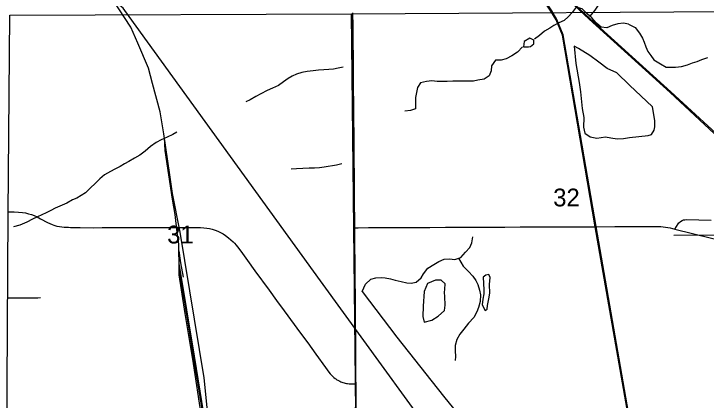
# Model space of a CAD drawing. Extents: x 0 to 40.2, y 0 to 22.
# Drawn here: x 2.971 to 4.597, y 16.354 to 17.261 of the extents above; entities that cross this region are included whole.
import ezdxf

# ---------------------------------------------------------------- set-up
doc = ezdxf.new("R2010")
doc.units = 0
for name, color, linetype in [('GM_X_City_Street', 7, 'Continuous'), ('GM_X_Corporation', 7, 'Continuous'), ('GM_X_Major_Lake_Text', 7, 'Continuous'), ('GM_X_Major_River', 7, 'Continuous'), ('GM_X_Minor_Lake', 7, 'Continuous'), ('GM_X_Minor_Lake_Text', 7, 'Continuous'), ('GM_X_Rail_Line', 7, 'Continuous'), ('GM_X_Unincorporated_Location', 7, 'Continuous')]:
    doc.layers.add(name, color=color, linetype=linetype)

msp = doc.modelspace()

# ---------------------------------------------------------------- linework, layer by layer
at = {"layer": 'GM_X_Corporation'}
for points in [[(2.9622, 17.2582), (3.7642, 17.2609), (3.7748, 16.2549), (3.7456, 16.2537), (2.955, 16.2539), (2.9579, 16.7917)], [(4.773, 17.2675), (4.7705, 16.2552), (4.7398, 16.2563), (3.7748, 16.2549), (3.7642, 17.2609)]]:
    msp.add_lwpolyline(points, close=True, dxfattribs=at)
at = {"layer": 'GM_X_Major_Lake_Text'}
for points in [[(3.768, 17.2235), (3.7677, 17.2315), (3.7674, 17.2634)], [(3.772, 16.7585), (3.7718, 16.779), (3.7713, 16.8131), (3.771, 16.8809), (3.7704, 16.9176), (3.7703, 16.9455), (3.7703, 16.9759), (3.7699, 17.0132), (3.7698, 17.0299), (3.7695, 17.0489), (3.7692, 17.0873), (3.7687, 17.1333), (3.7686, 17.1507), (3.7686, 17.1644), (3.7683, 17.188), (3.768, 17.2235)], [(3.7748, 16.3921), (3.7747, 16.4005), (3.7747, 16.4061), (3.7747, 16.4142), (3.7745, 16.4241), (3.7744, 16.431), (3.7743, 16.4378), (3.7742, 16.4453), (3.7741, 16.4558), (3.774, 16.462), (3.7741, 16.4689), (3.7741, 16.4881), (3.7741, 16.4943), (3.774, 16.5049), (3.7737, 16.5322), (3.7736, 16.5416), (3.7735, 16.5546), (3.7733, 16.5764), (3.7733, 16.6031), (3.7731, 16.6285), (3.7727, 16.6596), (3.7726, 16.6758), (3.7723, 16.718), (3.772, 16.7585)], [(3.767, 16.2555), (3.7693, 16.2747), (3.7715, 16.2932), (3.7729, 16.3087), (3.7739, 16.3273), (3.7746, 16.3484), (3.7748, 16.3688), (3.7748, 16.3921)]]:
    msp.add_lwpolyline(points, dxfattribs=at)
at = {"layer": 'GM_X_Major_River'}
for p, q in [((3.3597, 16.6749), (3.359, 16.7047)), ((3.3595, 16.6608), (3.3597, 16.6749))]:
    msp.add_line(p, q, dxfattribs=at)
for points in [[(3.4275, 16.3124), (3.4214, 16.3755), (3.4184, 16.4064), (3.362, 16.7482), (3.3443, 16.8388), (3.338, 16.8832), (3.3236, 16.9789), (3.3149, 17.0308), (3.2968, 17.0973), (3.2873, 17.1335), (3.2626, 17.1924), (3.2465, 17.2295), (3.2047, 17.2941), (3.141, 17.3854), (3.1259, 17.4137)], [(4.4984, 15.8177), (4.4509, 16.1036), (4.3365, 16.7608), (4.2596, 17.2111), (4.2446, 17.2471), (4.2325, 17.2675), (4.2194, 17.2862), (4.173, 17.3292), (4.0811, 17.4144)], [(4.5011, 15.819), (4.4528, 16.1039), (4.3383, 16.7612), (4.2614, 17.2116), (4.2462, 17.2479), (4.2341, 17.2685), (4.2208, 17.2874), (4.1742, 17.3305), (4.0824, 17.4158)], [(4.1455, 17.415), (4.1542, 17.4069), (4.3224, 17.2484), (4.5126, 17.0764), (4.6277, 16.9694), (4.7733, 16.8366), (5.084, 16.5474), (5.609, 16.0605), (6.0377, 15.6628), (6.1678, 15.5423), (6.5654, 15.1729), (7.036, 14.7358), (7.4144, 14.3845), (7.7209, 14.1)], [(4.1471, 17.4167), (4.1558, 17.4086), (4.3239, 17.2501), (4.5142, 17.0781), (4.6293, 16.9711), (4.7748, 16.8383), (5.0856, 16.5491), (5.6113, 16.0632), (6.0399, 15.6663), (6.1698, 15.5443), (6.5669, 15.1758), (7.0383, 14.7375), (7.4155, 14.3872), (7.7237, 14.1)], [(4.038, 16.1564), (3.6914, 16.634), (3.2424, 17.2551), (3.2285, 17.2744), (3.2047, 17.2941), (3.2047, 17.2941)], [(3.359, 16.7047), (3.3587, 16.7201), (3.3551, 16.7486), (3.3499, 16.7896), (3.3438, 16.8261), (3.3264, 16.9404), (3.3248, 16.9706)], [(3.359, 16.7047), (3.3629, 16.676), (3.3692, 16.6423)], [(3.4589, 16.0459), (3.4545, 16.0592), (3.4492, 16.091), (3.4327, 16.1992), (3.4113, 16.3207), (3.3929, 16.4395), (3.3737, 16.5572), (3.3594, 16.6481), (3.3595, 16.6608)], [(3.3595, 16.6608), (3.4178, 16.3037), (3.4589, 16.0459)], [(3.4645, 16.0288), (3.4574, 16.0724), (3.4178, 16.3218), (3.3959, 16.4573), (3.3597, 16.6749)]]:
    msp.add_lwpolyline(points, dxfattribs=at)
at = {"layer": 'GM_X_Minor_Lake'}
for points in [[(4.3552, 17.414), (4.3675, 17.393), (4.3729, 17.3801), (4.3736, 17.3706), (4.3761, 17.361), (4.379, 17.3485), (4.3788, 17.336), (4.3707, 17.3224), (4.3626, 17.3096), (4.353, 17.2964), (4.3352, 17.2701), (4.3239, 17.256)], [(4.4141, 17.2369), (4.4025, 17.2393), (4.3896, 17.2375), (4.3763, 17.2339), (4.3638, 17.2284), (4.3502, 17.2297), (4.339, 17.2393), (4.3286, 17.252), (4.3177, 17.2612), (4.3054, 17.2728), (4.2915, 17.2767), (4.2823, 17.2643), (4.2731, 17.2538), (4.2635, 17.2452), (4.2506, 17.2401), (4.2392, 17.2337), (4.2297, 17.2278), (4.2175, 17.2207), (4.2053, 17.2103), (4.1934, 17.2017)], [(4.4141, 17.2369), (4.4303, 17.2288), (4.4403, 17.2154), (4.4473, 17.2039), (4.4513, 17.1943), (4.4549, 17.1836), (4.46, 17.1729), (4.4667, 17.163), (4.4741, 17.153), (4.4898, 17.1433), (4.5029, 17.1358), (4.5147, 17.1356), (4.5245, 17.1362), (4.5389, 17.1375), (4.553, 17.1415), (4.5644, 17.1458), (4.5754, 17.1495), (4.5868, 17.1538), (4.6005, 17.1589)], [(4.1656, 17.1838), (4.1541, 17.1711), (4.1408, 17.1621), (4.1275, 17.1551), (4.1153, 17.1522), (4.1025, 17.1524), (4.0925, 17.1392), (4.092, 17.1271), (4.0873, 17.1154), (4.0755, 17.1079), (4.0611, 17.1051), (4.0508, 17.1029), (4.027, 17.1032), (4.0142, 17.103), (4.0017, 17.1028), (3.9889, 17.1018), (3.9772, 17.102), (3.9651, 17.1025), (3.9526, 17.1038), (3.9401, 17.1024), (3.9265, 17.0988), (3.9188, 17.0883), (3.9164, 17.0762), (3.9147, 17.0644), (3.9144, 17.0382), (3.9026, 17.0342), (3.8894, 17.0325)], [(3.7445, 17.136), (3.7328, 17.1335), (3.7218, 17.1314), (3.7108, 17.1304), (3.6995, 17.1294), (3.687, 17.1288), (3.6738, 17.127), (3.6598, 17.1253), (3.6476, 17.1236), (3.6347, 17.1195), (3.6252, 17.1147), (3.6153, 17.1092), (3.6047, 17.1017), (3.5928, 17.0931), (3.5788, 17.0865), (3.5659, 17.0809), (3.5514, 17.0735), (3.5396, 17.0669), (3.5259, 17.0591), (3.5164, 17.0542)], [(3.3542, 16.9831), (3.3446, 16.9775), (3.3317, 16.9712), (3.3176, 16.9649), (3.3055, 16.9586), (3.2925, 16.9493), (3.2799, 16.9384), (3.2673, 16.9295), (3.2547, 16.9221), (3.2418, 16.9143), (3.2312, 16.9091), (3.2213, 16.9028), (3.2087, 16.8965), (3.1981, 16.8909), (3.1843, 16.8831), (3.1736, 16.8734), (3.1625, 16.8625), (3.1515, 16.8524), (3.14, 16.8408), (3.1293, 16.8345), (3.119, 16.8278), (3.1095, 16.8241), (3.0958, 16.8163), (3.0685, 16.8045), (3.0586, 16.7993), (3.0476, 16.7938), (3.0369, 16.7893), (3.0267, 16.7842), (3.0152, 16.7786), (3.0023, 16.7716), (2.9852, 16.7649), (2.9704, 16.761)], [(3.7412, 16.9091), (3.729, 16.9059), (3.6999, 16.9009), (3.6889, 16.8995), (3.6772, 16.8989), (3.6651, 16.8987), (3.6496, 16.8981), (3.6348, 16.8972), (3.6224, 16.8962)], [(5.7069, 16.7385), (5.4235, 16.7393), (5.2105, 16.7393), (5.0119, 16.7384), (4.8526, 16.7394), (4.6942, 16.7408), (4.5209, 16.7402)], [(3.7889, 16.609), (3.7971, 16.6261), (3.8094, 16.6381), (3.8211, 16.6413), (3.8336, 16.6419), (3.8434, 16.641), (3.8559, 16.639), (3.8664, 16.6358), (3.8807, 16.6326), (3.8943, 16.629), (3.9045, 16.6281), (3.9162, 16.6306), (3.9277, 16.6407), (3.9335, 16.6505), (3.9434, 16.6633), (3.9572, 16.6719), (3.969, 16.6793), (3.9815, 16.6845), (3.9944, 16.6854), (4.0068, 16.6841), (4.0205, 16.6885), (4.032, 16.7009), (4.0419, 16.7122), (4.0466, 16.7235), (4.0494, 16.7371)], [(4.015, 16.6868), (4.0266, 16.6687), (4.0389, 16.656), (4.0494, 16.6445), (4.0557, 16.635), (4.0604, 16.6254), (4.0648, 16.6117), (4.0669, 16.601), (4.066, 16.5855), (4.0624, 16.5715), (4.0585, 16.5609), (4.0515, 16.5481), (4.0392, 16.5346), (4.0281, 16.5203), (4.0185, 16.5083), (4.0111, 16.4963), (4.0079, 16.4823), (4.0078, 16.4697), (4.0084, 16.4564), (4.0079, 16.447)], [(3.7889, 16.609), (3.8703, 16.5018), (3.9803, 16.3631), (4.0138, 16.3217)]]:
    msp.add_lwpolyline(points, dxfattribs=at)
at = {"layer": 'GM_X_Minor_Lake_Text'}
for p, q in [((4.18, 17.1833), (4.1845, 17.1847)), ((3.9824, 16.6067), (3.9832, 16.6142)), ((4.075, 16.6131), (4.0745, 16.6032))]:
    msp.add_line(p, q, dxfattribs=at)
for points in [[(4.1845, 17.1847), (4.1921, 17.1907), (4.1919, 17.199), (4.1829, 17.2037), (4.1692, 17.1963), (4.1683, 17.1834), (4.18, 17.1833)], [(4.4172, 17.0936), (4.3873, 17.1222), (4.364, 17.1327), (4.345, 17.1474), (4.3233, 17.1632), (4.2974, 17.1799), (4.2869, 17.1849), (4.2909, 17.1447), (4.2983, 17.1002), (4.3021, 17.0777), (4.3054, 17.0386), (4.3093, 17.0177), (4.309, 16.9949), (4.3118, 16.9805), (4.3245, 16.972), (4.34, 16.9687), (4.3608, 16.9719), (4.3732, 16.9702), (4.3879, 16.9674), (4.4027, 16.9679), (4.4171, 16.9703)], [(4.4171, 16.9703), (4.4606, 16.9754), (4.4686, 16.978), (4.4747, 16.9882), (4.4759, 16.9957), (4.476, 17.0102), (4.4709, 17.0428), (4.4172, 17.0936)], [(4.0745, 16.6032), (4.0721, 16.5907), (4.0711, 16.5778), (4.0778, 16.5645), (4.0827, 16.5671), (4.0836, 16.5762), (4.0864, 16.5913), (4.0889, 16.6046), (4.088, 16.6251), (4.0897, 16.6421), (4.0868, 16.649), (4.0792, 16.6476), (4.0735, 16.6423), (4.075, 16.6131)], [(3.9832, 16.6142), (3.9838, 16.6271), (3.9744, 16.6356), (3.9612, 16.6354), (3.9426, 16.6273), (3.9344, 16.6092), (3.9328, 16.5747), (3.9318, 16.5504), (3.9346, 16.5371), (3.9524, 16.5418), (3.9673, 16.5507), (3.9822, 16.5642), (3.9842, 16.577), (3.9834, 16.5968), (3.9824, 16.6067)]]:
    msp.add_lwpolyline(points, dxfattribs=at)
at = {"layer": 'GM_X_Rail_Line'}
for points in [[(2.957, 16.7962), (2.9726, 16.796), (2.9826, 16.7954), (2.9919, 16.7945), (2.9987, 16.7934), (3.006, 16.7916), (3.0126, 16.7896), (3.0191, 16.787), (3.0259, 16.784), (3.0339, 16.7799), (3.0505, 16.7712), (3.0558, 16.7687), (3.0614, 16.7661), (3.0655, 16.7644), (3.0726, 16.7623), (3.0787, 16.7613), (3.0838, 16.7607), (3.0899, 16.7602), (3.0999, 16.7597), (3.1043, 16.7595), (3.1122, 16.7594), (3.1272, 16.759), (3.1589, 16.7588), (3.1789, 16.7589), (3.2302, 16.7592), (3.2513, 16.7593), (3.2661, 16.7591), (3.3014, 16.7589), (3.3373, 16.759), (3.3523, 16.759), (3.3722, 16.7589), (3.3952, 16.759), (3.4095, 16.7589), (3.4177, 16.7583), (3.4245, 16.7575), (3.4309, 16.7565), (3.4372, 16.755), (3.4439, 16.7529), (3.4507, 16.7503), (3.4563, 16.7477), (3.4625, 16.7442), (3.4685, 16.7401), (3.4751, 16.7353), (3.4809, 16.7306), (3.486, 16.7258), (3.4894, 16.7222), (3.4935, 16.7176), (3.4967, 16.7135), (3.504, 16.7035), (3.5197, 16.6818), (3.5376, 16.6572), (3.5711, 16.6116), (3.5884, 16.588), (3.6059, 16.5638), (3.6444, 16.5111), (3.6614, 16.4882), (3.6803, 16.4619), (3.7028, 16.4305), (3.7113, 16.4193), (3.7142, 16.4158), (3.7166, 16.4131), (3.7187, 16.411), (3.7207, 16.4092), (3.723, 16.4071), (3.7256, 16.4048), (3.7276, 16.4034), (3.7301, 16.4017), (3.7324, 16.4003), (3.7349, 16.3989), (3.737, 16.3979), (3.7393, 16.3968), (3.7418, 16.3958), (3.7439, 16.3951), (3.7467, 16.3942), (3.7495, 16.3935), (3.7522, 16.3929), (3.7551, 16.3925), (3.7587, 16.3922), (3.7623, 16.3921), (3.7659, 16.3921), (3.7721, 16.3921), (3.7748, 16.3921)], [(3.772, 16.7585), (3.7801, 16.7586), (3.8043, 16.7589), (3.8317, 16.7592), (3.8534, 16.7592), (3.869, 16.7594), (3.8889, 16.7593), (3.948, 16.7595), (3.9846, 16.7599), (4.0269, 16.7599), (4.0599, 16.7599), (4.0932, 16.7601), (4.1245, 16.7603), (4.16, 16.7604), (4.1967, 16.7605), (4.234, 16.7606), (4.2663, 16.7607), (4.308, 16.7608), (4.3403, 16.7609), (4.3826, 16.7612), (4.4284, 16.7613), (4.4907, 16.7615), (4.5126, 16.7581), (4.5231, 16.7555), (4.6957, 16.7129)], [(3.7748, 16.3921), (3.7747, 16.4005), (3.7747, 16.4061), (3.7747, 16.4142), (3.7745, 16.4241), (3.7744, 16.431), (3.7743, 16.4378), (3.7742, 16.4453), (3.7741, 16.4558), (3.774, 16.462), (3.7741, 16.4689), (3.7741, 16.4881), (3.7741, 16.4943), (3.774, 16.5049), (3.7737, 16.5322), (3.7736, 16.5416), (3.7735, 16.5546), (3.7733, 16.5764), (3.7733, 16.6031), (3.7731, 16.6285), (3.7727, 16.6596), (3.7726, 16.6758), (3.7723, 16.718), (3.772, 16.7585)]]:
    msp.add_lwpolyline(points, dxfattribs=at)
at = {"layer": 'GM_X_Unincorporated_Location'}
for points in [[(4.5231, 16.7555), (4.5307, 16.7677), (4.5323, 16.7699), (4.5346, 16.7719), (4.5367, 16.7735), (4.5405, 16.7759), (4.5435, 16.7769), (4.5471, 16.7776), (4.5504, 16.7779), (4.6083, 16.7767)], [(2.9564, 16.5939), (2.9758, 16.5943), (2.9888, 16.5943), (3.0112, 16.594), (3.0278, 16.5942), (3.034, 16.5945)]]:
    msp.add_lwpolyline(points, dxfattribs=at)

# ---------------------------------------------------------------- texts
at = {"layer": 'GM_X_City_Street'}
for s, p in [('32', (4.2377, 16.8088)), ('31', (3.3314, 16.7217))]:
    msp.add_text(s, height=0.04186, rotation=0, dxfattribs=at).set_placement(p)

doc.saveas('drawing.dxf')
